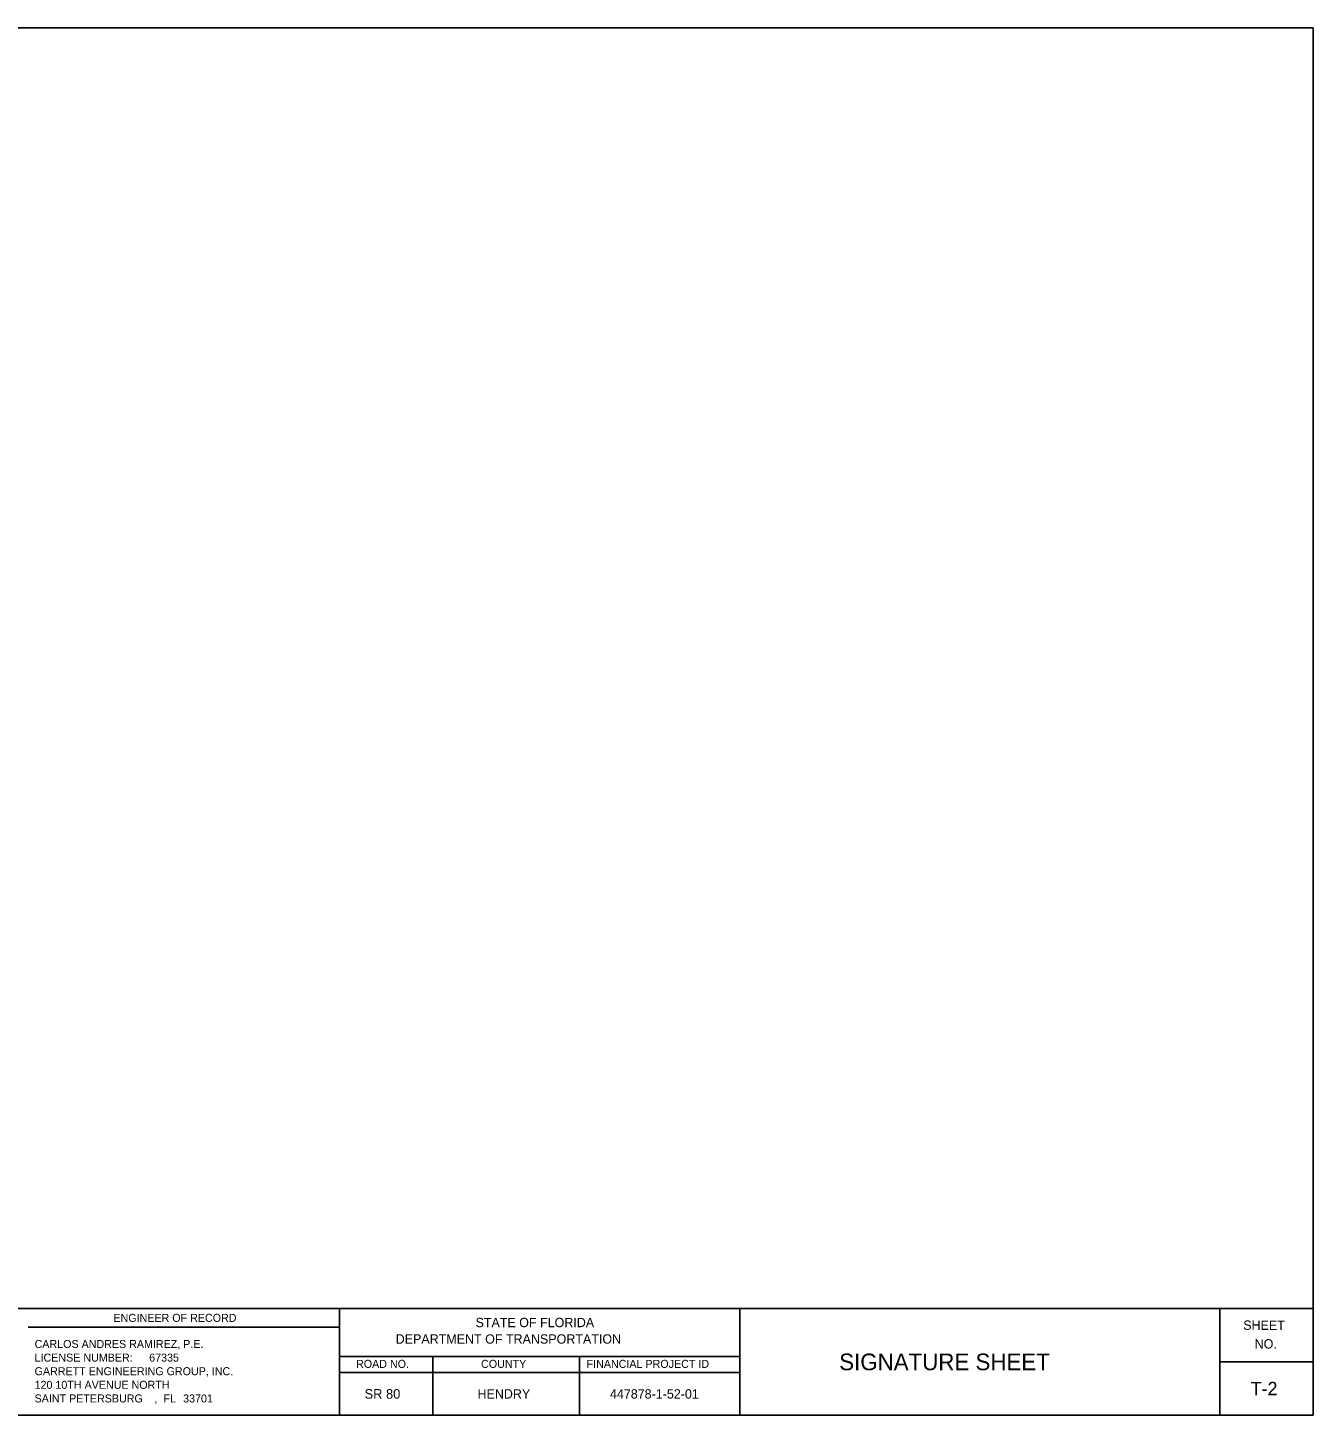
# Model space of a CAD drawing. Extents: x -0.86 to 1.33, y -1.26 to 1.83.
# Drawn here: x 0.526 to 1.329, y 0.004 to 0.871 of the extents above; entities that cross this region are included whole.
import ezdxf

# ---------------------------------------------------------------- set-up
doc = ezdxf.new("R2010")
doc.units = 0
for name, color, linetype in [('SheetBorder_dp', 7, 'Continuous'), ('SheetLines_dp', 7, 'Continuous'), ('TextMisc', 7, 'Continuous'), ('TextNotes', 7, 'Continuous')]:
    doc.layers.add(name, color=color, linetype=linetype)

msp = doc.modelspace()

# ---------------------------------------------------------------- linework, layer by layer
at = {"layer": 'SheetBorder_dp'}
for p, q in [((0.72083, 0.07083), (0.72083, 0.00417)), ((0.97083, 0.00417), (0.97083, 0.07083)), ((1.27083, 0.00417), (1.27083, 0.07083)), ((0.52621, 0.05917), (0.72084, 0.05917)), ((0.72083, 0.04083), (0.97083, 0.04083)), ((0.77916, 0.04083), (0.77916, 0.00417)), ((0.87083, 0.04083), (0.87083, 0.00417)), ((1.27083, 0.0375), (1.32916, 0.0375)), ((0.72083, 0.03083), (0.97083, 0.03083))]:
    msp.add_line(p, q, dxfattribs=at)
at = {"layer": 'TextNotes'}
for p, q in [((0.04583, 0.87083), (1.32916, 0.87083)), ((1.32916, 0.87083), (1.32916, 0.00417)), ((0.04583, 0.07083), (1.32916, 0.07083)), ((0.04583, 0.00417), (1.32916, 0.00417))]:
    msp.add_line(p, q, dxfattribs=at)

# ---------------------------------------------------------------- texts
at = {"layer": 'SheetLines_dp'}
msp.add_text('T-2', height=0.00833, dxfattribs=at).set_placement((1.2901, 0.01667))
at = {"layer": 'TextMisc'}
for s, height, p in [('ENGINEER OF RECORD', 0.005, (0.57954, 0.0625)), ('STATE OF FLORIDA', 0.0058333, (0.80578, 0.05918)), ('DEPARTMENT OF TRANSPORTATION', 0.0058333, (0.75589, 0.04888)), ('CARLOS ANDRES RAMIREZ, P.E.', 0.005, (0.5303, 0.04617)), ('LICENSE NUMBER: ', 0.005, (0.5303, 0.03767)), ('67335', 0.005, (0.60189, 0.03767)), ('ROAD NO.', 0.005, (0.73115, 0.03376)), ('COUNTY', 0.005, (0.80925, 0.03376)), ('FINANCIAL PROJECT ID', 0.005, (0.87518, 0.03376)), ('SIGNATURE SHEET', 0.0104166, (1.03299, 0.03229)), ('GARRETT ENGINEERING GROUP, INC.', 0.005, (0.5303, 0.02917)), ('120 10TH AVENUE NORTH', 0.005, (0.5303, 0.02067)), ('SR 80', 0.006, (0.73648, 0.0145)), ('HENDRY', 0.005833, (0.80701, 0.01458)), ('447878-1-52-01', 0.0058331, (0.88977, 0.01458)), ('SAINT PETERSBURG', 0.005, (0.5303, 0.01216)), (', ', 0.005, (0.60514, 0.01216)), ('FL', 0.005, (0.61083, 0.01216)), ('33701', 0.005, (0.6231, 0.01216))]:
    msp.add_text(s, height=height, dxfattribs=at).set_placement(p)
for s, p in [('SHEET', (1.2854, 0.05754)), ('NO.', (1.29254, 0.04586))]:
    msp.add_text(s, height=0.005833, rotation=359.86066, dxfattribs=at).set_placement(p)

doc.saveas('drawing.dxf')
